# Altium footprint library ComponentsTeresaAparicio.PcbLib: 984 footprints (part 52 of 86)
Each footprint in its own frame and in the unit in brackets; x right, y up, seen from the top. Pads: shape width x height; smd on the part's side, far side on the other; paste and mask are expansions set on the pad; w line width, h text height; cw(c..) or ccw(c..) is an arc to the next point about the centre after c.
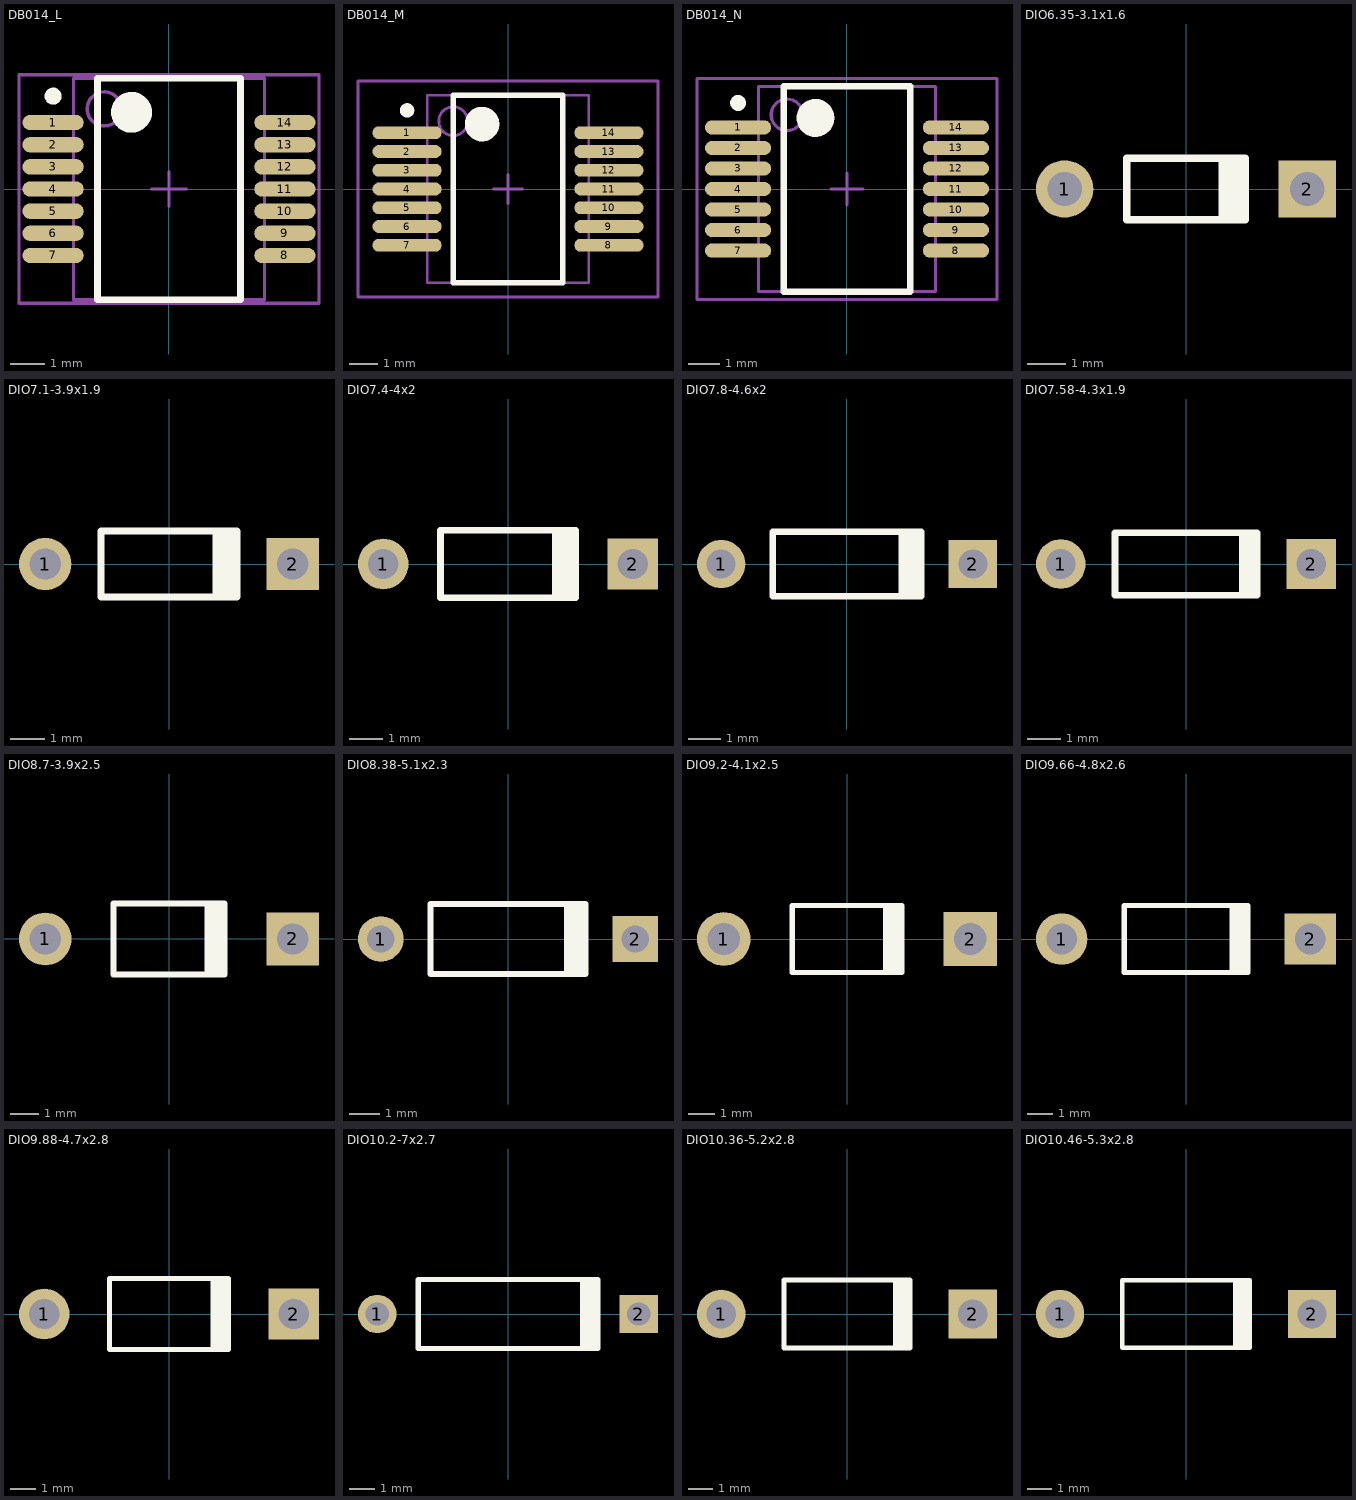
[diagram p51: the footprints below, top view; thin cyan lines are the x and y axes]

## DB014_L [mm] "SOP, 14-Leads, Body 6.2x5.3mm, Pitch 0.65mm, IPC High Density"
height 2
pads (14):
  oval 1.8x0.45 smd: 1(-3.4,1.95) 2(-3.4,1.3) 3(-3.4,0.65) 4(-3.4,0) 5(-3.4,-0.65) 6(-3.4,-1.3) 7(-3.4,-1.95) 8(3.4,-1.95) 9(3.4,-1.3) 10(3.4,-0.65) 11(3.4,0) 12(3.4,0.65) 13(3.4,1.3) 14(3.4,1.95)
Top Overlay:
  circle w0.6: c-1.1,2.25 r0.3
  circle w0.25: c-3.4,2.725 r0.125
  lines w0.2: -2.1,-3.25 2.1,-3.25 2.1,3.25 -2.1,3.25 -2.1,-3.25
Mechanical 13:
  circle w0.1: c-1.9,2.35 r0.5
  lines w0.1: -2.8,-3.25 2.8,-3.25 2.8,3.25 -2.8,3.25 -2.8,-3.25
Mechanical 15:
  lines w0.1: -0.5,0 0.5,0 ; 0,-0.5 0,0.5 ; -4.4,-3.35 4.4,-3.35 4.4,3.35 -4.4,3.35 -4.4,-3.35
3D body: height 2, standoff 0, extent -2.8,-3.25 2.8,3.25

## DB014_M [mm] "SOP, 14-Leads, Body 6.2x5.3mm, Pitch 0.65mm, IPC Low Density"
height 2
pads (14):
  oval 2.4x0.45 smd: 1(-3.5,1.95) 2(-3.5,1.3) 3(-3.5,0.65) 4(-3.5,0) 5(-3.5,-0.65) 6(-3.5,-1.3) 7(-3.5,-1.95) 8(3.5,-1.95) 9(3.5,-1.3) 10(3.5,-0.65) 11(3.5,0) 12(3.5,0.65) 13(3.5,1.3) 14(3.5,1.95)
Top Overlay:
  circle w0.25: c-3.5,2.725 r0.125
  circle w0.6: c-0.9,2.25 r0.3
  lines w0.2: -1.9,-3.25 -1.9,3.25 1.9,3.25 1.9,-3.25 -1.9,-3.25
Mechanical 13:
  circle w0.1: c-1.9,2.35 r0.5
  lines w0.1: -2.8,-3.25 -2.8,3.25 2.8,3.25 2.8,-3.25 -2.8,-3.25
Mechanical 15:
  lines w0.1: -0.5,0 0.5,0 ; 0,-0.5 0,0.5 ; -5.2,-3.75 -5.2,3.75 5.2,3.75 5.2,-3.75 -5.2,-3.75
3D body: height 2, standoff 0, extent -2.8,-3.25 2.8,3.25

## DB014_N [mm] "SOP, 14-Leads, Body 6.2x5.3mm, Pitch 0.65mm, IPC Medium Density"
height 2
pads (14):
  oval 2.1x0.45 smd: 1(-3.45,1.95) 2(-3.45,1.3) 3(-3.45,0.65) 4(-3.45,0) 5(-3.45,-0.65) 6(-3.45,-1.3) 7(-3.45,-1.95) 8(3.45,-1.95) 9(3.45,-1.3) 10(3.45,-0.65) 11(3.45,0) 12(3.45,0.65) 13(3.45,1.3) 14(3.45,1.95)
Top Overlay:
  circle w0.6: c-1,2.25 r0.3
  circle w0.25: c-3.45,2.725 r0.125
  lines w0.2: -2,-3.25 2,-3.25 2,3.25 -2,3.25 -2,-3.25
Mechanical 13:
  circle w0.1: c-1.9,2.35 r0.5
  lines w0.1: -2.8,-3.25 2.8,-3.25 2.8,3.25 -2.8,3.25 -2.8,-3.25
Mechanical 15:
  lines w0.1: -0.5,0 0.5,0 ; 0,-0.5 0,0.5 ; -4.75,-3.5 4.75,-3.5 4.75,3.5 -4.75,3.5 -4.75,-3.5
3D body: height 2, standoff 0, extent -2.8,-3.25 2.8,3.25

## DIO6.35-3.1x1.6 [mm] "Diode, Axial; Body 3 x 1.6 mm (LxDia. max), Lead Dia. 0.55 mm (max)"
height 1.6
pads (2):
  round 1.5 hole 0.9: 1(-3.175,0)
  rect 1.5x1.5 hole 0.9: 2(3.175,0)
Top Overlay:
  rectangle: 0.85,-0.8 1.65,0.8
  lines w0.2: 1.55,-0.8 -1.55,-0.8 -1.55,0.8 1.55,0.8

## DIO7.1-3.9x1.9 [mm] "Diode, Axial; Body 3.8 x 1.9 mm (LxDia. max), Lead Dia. 0.53 mm (max)"
height 1.9
pads (2):
  round 1.5 hole 0.9: 1(-3.55,0)
  rect 1.5x1.5 hole 0.9: 2(3.55,0)
Top Overlay:
  rectangle: 1.25,-0.95 2.05,0.95
  lines w0.2: 1.95,-0.95 -1.95,-0.95 -1.95,0.95 1.95,0.95

## DIO7.4-4x2 [mm] "Diode, Axial; Body 4 x 2 mm (LxDia. max), Lead Dia. 0.6 mm (max)"
height 2
pads (2):
  round 1.5 hole 0.9: 1(-3.7,0)
  rect 1.5x1.5 hole 0.9: 2(3.7,0)
Top Overlay:
  rectangle: 1.3,-1 2.1,1
  lines w0.2: 2,-1 -2,-1 -2,1 2,1

## DIO7.8-4.6x2 [mm] "Diode, Axial; Body 4.6 x 1.9 mm (LxDia. max), Lead Dia. 0.53 mm (max)"
height 2
pads (2):
  round 1.5 hole 0.9: 1(-3.9,0)
  rect 1.5x1.5 hole 0.9: 2(3.9,0)
Top Overlay:
  rectangle: 1.6,-1 2.4,1
  lines w0.2: 2.3,-1 -2.3,-1 -2.3,1 2.3,1

## DIO7.58-4.3x1.9 [mm] "Diode, Axial; Body 4.3 x 1.9 mm (LxDia. max), Lead Dia. 0.56 mm (max)"
height 1.9
pads (2):
  round 1.5 hole 0.9: 1(-3.79,0)
  rect 1.5x1.5 hole 0.9: 2(3.79,0)
Top Overlay:
  rectangle: 1.6,-0.95 2.25,0.95
  lines w0.2: 2.15,-0.95 -2.15,-0.95 -2.15,0.95 2.15,0.95

## DIO8.7-3.9x2.5 [mm] "Diode, Axial; Body 3.9 x 2.5 mm (LxDia. max), Lead Dia. 0.8 mm (max)"
height 2.5
pads (2):
  round 1.85 hole 1.1: 1(-4.35,0)
  rect 1.85x1.85 hole 1.1: 2(4.35,0)
Top Overlay:
  rectangle: 1.25,-1.25 2.05,1.25
  lines w0.2: 1.95,-1.25 -1.95,-1.25 -1.95,1.25 1.95,1.25

## DIO8.38-5.1x2.3 [mm] "Diode, Axial; Body 5.1 x 2.3 mm (LxDia. max), Lead Dia. 0.56 mm (max)"
height 2.3
pads (2):
  round 1.5 hole 0.9: 1(-4.19,0)
  rect 1.5x1.5 hole 0.9: 2(4.19,0)
Top Overlay:
  rectangle: 1.85,-1.15 2.65,1.15
  lines w0.2: 2.55,-1.15 -2.55,-1.15 -2.55,1.15 2.55,1.15

## DIO9.2-4.1x2.5 [mm] "Diode, Axial; Body 4.1 x 2.5 mm (LxDia. max), Lead Dia. 0.85 mm (max)"
height 2.5
pads (2):
  round 2 hole 1.2: 1(-4.6,0)
  rect 2x2 hole 1.2: 2(4.6,0)
Top Overlay:
  rectangle: 1.35,-1.25 2.15,1.25
  lines w0.2: 2.05,-1.25 -2.05,-1.25 -2.05,1.25 2.05,1.25

## DIO9.66-4.8x2.6 [mm] "Diode, Axial; Body 4.8 x 2.6 mm (LxDia. max), Lead Dia. 0.81 mm (max)"
height 2.6
pads (2):
  round 2 hole 1.2: 1(-4.83,0)
  rect 2x2 hole 1.2: 2(4.83,0)
Top Overlay:
  rectangle: 1.7,-1.3 2.5,1.3
  lines w0.2: 2.4,-1.3 -2.4,-1.3 -2.4,1.3 2.4,1.3

## DIO9.88-4.7x2.8 [mm] "Diode, Axial; Body 4.7 x 2.7 mm (LxDia. max), Lead Dia. 0.86 mm (max)"
height 2.8
pads (2):
  round 2 hole 1.2: 1(-4.94,0)
  rect 2x2 hole 1.2: 2(4.94,0)
Top Overlay:
  rectangle: 1.65,-1.4 2.45,1.4
  lines w0.2: 2.35,-1.4 -2.35,-1.4 -2.35,1.4 2.35,1.4

## DIO10.2-7x2.7 [mm] "Diode, Axial; Body 7 x 2.7 mm (LxDia. max), Lead Dia. 0.53 mm (max)"
height 2.7
pads (2):
  round 1.5 hole 0.9: 1(-5.1,0)
  rect 1.5x1.5 hole 0.9: 2(5.1,0)
Top Overlay:
  rectangle: 2.8,-1.35 3.6,1.35
  lines w0.2: 3.5,-1.35 -3.5,-1.35 -3.5,1.35 3.5,1.35

## DIO10.36-5.2x2.8 [mm] "Diode, Axial; Body 5.2 x 2.7 mm (LxDia. max), Lead Dia. 0.86 mm (max)"
height 2.8
pads (2):
  round 2 hole 1.2: 1(-5.18,0)
  rect 2x2 hole 1.2: 2(5.18,0)
Top Overlay:
  rectangle: 1.9,-1.4 2.7,1.4
  lines w0.2: 2.6,-1.4 -2.6,-1.4 -2.6,1.4 2.6,1.4

## DIO10.46-5.3x2.8 [mm] "Diode, Axial; Body 5.2 x 2.7 mm (LxDia. max), Lead Dia. 0.86 mm (max)"
height 2.8
pads (2):
  round 2 hole 1.2: 1(-5.23,0)
  rect 2x2 hole 1.2: 2(5.23,0)
Top Overlay:
  rectangle: 1.95,-1.4 2.75,1.4
  lines w0.2: 2.65,-1.4 -2.65,-1.4 -2.65,1.4 2.65,1.4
